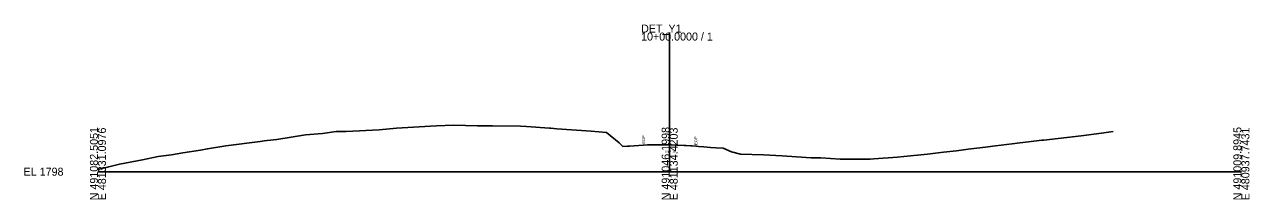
# Model space of a CAD drawing. Extents: x -26 to 403, y -10 to 3149.
# Drawn here: x -25.7 to 402.8, y -9.7 to 51.4 of the extents above; entities that cross this region are included whole.
import ezdxf

# ---------------------------------------------------------------- set-up
doc = ezdxf.new("R2010")
doc.units = 0
for name, color, linetype in [('Exist Cross Section Cell', 7, 'Continuous'), ('Exist XS Center Line Elevation Label', 7, 'Continuous'), ('Exist XS Ground Line', 7, 'Continuous'), ('Scratch_Level_3', 7, 'Continuous')]:
    doc.layers.add(name, color=color, linetype=linetype)

msp = doc.modelspace()

# ---------------------------------------------------------------- linework, layer by layer
at = {"layer": 'Exist Cross Section Cell'}
for p, q in [((200, 0), (200, 48.58)), ((0, 0), (200, 0)), ((200, 0), (400, 0))]:
    msp.add_line(p, q, dxfattribs=at)
at = {"layer": 'Exist XS Ground Line'}
msp.add_lwpolyline([(0, 0.77), (3.76, 1.72), (7.56, 2.59), (15.58, 4.14), (21.1, 5.28), (25.75, 5.92), (29.69, 6.54), (35.92, 7.57), (38.27, 8), (44.79, 9.02), (56.78, 10.55), (58.16, 10.72), (59.17, 10.84), (62.55, 11.29), (72.62, 12.84), (78.55, 13.39), (83.33, 14.05), (86.78, 14.02), (98.37, 14.64), (104.44, 15.14), (116.39, 15.89), (118.45, 16.01), (124.37, 16.19), (132.72, 16.01), (138.05, 16), (147.8, 15.84), (149.89, 15.73), (157.97, 15.19), (158.48, 15.14), (160.49, 15.01), (172.53, 14.1), (177.95, 13.74), (182.31, 10.13), (183.56, 8.83), (185.24, 8.88), (186, 8.93), (187.6, 9.05), (190.89, 9.29), (192.22, 9.35), (194.34, 9.38), (194.77, 9.39), (195.39, 9.39), (197.3, 9.38), (198.7, 9.37), (199.97, 9.36), (200.57, 9.33), (202.36, 9.24), (202.88, 9.22), (205.03, 9.14), (205.73, 9.11), (207.44, 9.02), (207.84, 9), (209.13, 8.92), (210.14, 8.82), (211.99, 8.63), (214.29, 8.43), (216.18, 8.38), (218.69, 8.23), (221.64, 6.99), (224.76, 6.14), (232.8, 5.84), (239.34, 5.51), (244.34, 5.17), (249.51, 4.87), (252.92, 4.87), (259.68, 4.41), (261.51, 4.4), (270.1, 4.43), (271.41, 4.52), (279.65, 5.1), (281.97, 5.31), (290.19, 6.09), (295.85, 6.81), (300.37, 7.32), (304.44, 7.89), (310.54, 8.6), (313.03, 8.86), (320.71, 9.85), (321.61, 9.95), (326.51, 10.54), (330.2, 10.98), (330.88, 11.06), (343.93, 12.52), (351.02, 13.5), (355.18, 14.07)], dxfattribs=at)

# ---------------------------------------------------------------- texts
at = {"layer": 'Exist Cross Section Cell'}
for s, p in [('10+00.0000 / 1', (190, 45.78)), ('DET_Y1', (190, 48.58)), ('EL 1798', (-26, -1.4))]:
    msp.add_text(s, height=2.8, dxfattribs=at).set_placement(p)
for s, p in [('N 491082.5051', (0, -10)), ('E 481331.0976', (2.8, -10)), ('N 491046.1998', (200, -10)), ('E 481134.4203', (202.8, -10)), ('N 491009.8945', (400, -10)), ('E 480937.7431', (402.8, -10))]:
    msp.add_text(s, height=2.8, rotation=90, dxfattribs=at).set_placement(p)
at = {"layer": 'Exist XS Center Line Elevation Label'}
msp.add_text('1807.36', height=0.75, dxfattribs=at).set_placement((198.25, 6.61))
at = {"layer": 'Scratch_Level_3'}
for p in [(191.39, 9.29), (209.63, 8.92)]:
    msp.add_text('-EOP', height=1, rotation=90, dxfattribs=at).set_placement(p)

doc.saveas('drawing.dxf')
